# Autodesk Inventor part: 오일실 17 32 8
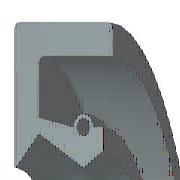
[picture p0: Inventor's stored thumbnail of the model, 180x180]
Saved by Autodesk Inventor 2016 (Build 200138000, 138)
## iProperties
IsCustomPart: 1
Created: 2012-02
Part Number: 오일실 17 32 8
Material: 고무
Description: 오일-실
Document SubType Name: Modeling
Standard: KS B 2804
Designer: mduedu
Standards Organization: KS
Language: ko-KR
Size Designation: D - 17 32 8
Categories: <MemberInstance><Categories><Category DisplayName="샤프트 부품" InternalName="7f7aeb1f-a693-4053-b835-cee3144e0d98" Mnemonic="SHFT"><Category DisplayName="실링" Intern
Density: 0.93 g/cm^3
Appearance: 고무 - 검은색 - 버전 1.1
Author: mduedu
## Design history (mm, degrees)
revolve "본체" stored, may be unused: angle "d17" = 90 deg
revolve "스프링1" stored, may be unused: angle "d18" = 90 deg
body "Solid1"
sketch "스케치1"
  geometry: L1 (0, 16)-(8, 16); L2 (8, 14.25)-(1.75, 14.25); L3 (1.75, 10.25)-(4.9, 8.5); L4 (4.9, 8.5)-(0, 8.5); L5 (0, 0)-(9.586, 0) reference; L6 (4.9, 8.5)-(6.3, 9.375); L7 (0, 18)-(0, -3) reference; L8 (-1.941, 0)-(11.507, 0) reference; L9 (4.2, 10.6)-(1.75, 11.21); L10 (1.75, 11.21)-(1.75, 14.25); L11 (0, 16)-(0, 8.588); L12 (4.9, 8.5)-(0, 8.5); L13 (1.75, 10.25)-(0.152, 8.528); L14 (8, 16)-(8, 14.25); L15 (5.6, 10.6)-(6.3, 10.6); L16 (6.3, 10.6)-(6.3, 9.375); C1 r 0.455 at (4.9, 10.6); A1 r 0.7 centre (4.9, 10.6) between (5.6, 10.6) and (4.2, 10.6); A2 r 0.088 centre (0.088, 8.588) between (0, 8.588) and (0.152, 8.528); 1 further point
  constraints: 28 end point, 5 horizontal alignment, 5 point on line, 4 point on circle, 4 vertical alignment, 3 centre point, 3 tangent, 2 collinear, 2 horizontal, 2 perpendicular, 1 coincident, 1 parallel
  dimensions: "d0" = 32 diameter of L1 L5 (= SD2); "d1" = 1.75 distance of L1.end L2.start (= SD); "d2" = 0.91 diameter of C1 (= SPDI); "d3" = 1.4 diameter of A1 (= SPDA); "d4" = 17 diameter of L3.end L5 (= NND); "d5" = 20.5 diameter of L3.start L5 (= TKDM); "d7" = 22.42 diameter of L9.end L5 (= TKDM + 0.24 x SWDT); "d8" = 1.75 distance between parallel lines of L11 L10 (= SD); "d9" = 4.9 distance from line of L11 C1.centre (= SPDST); "d10" = 21.2 diameter of C1.centre L5 (= HLDM); "d11" = 0.0875 radius of A2 (= 0.25 x LAB); "d12" = 6.3 distance between parallel lines of L11 L16 (= SDI); "d13" = 18.75 diameter of L6.end L5 (= ABDM); "d14" = 8 distance from line of L11 L1.end (= SWDT)
fillet "모깎기1" dims "d6" = 0.3 (= RR)
other parameters: "SD2" = 32 [user parameter; used in 1 equation term], "SWDT" = 8 [user parameter; used in 2 equation terms], "RR" = 0.3 [user parameter; used in 1 equation term], "SD" = 1.75 [user parameter; used in 2 equation terms], "NND" = 17 [user parameter; used in 1 equation term], "SPDA" = 1.4 [user parameter; used in 1 equation term], "SPDI" = 0.91 [user parameter; used in 1 equation term], "TKDM" = 20.5 [user parameter; used in 2 equation terms], "HLDM" = 21.2 [user parameter; used in 1 equation term], "ABDM" = 18.75 [user parameter; used in 1 equation term], "SDI" = 6.3 [user parameter; used in 1 equation term], "SPDST" = 4.9 [user parameter; used in 1 equation term], "LAB" = 0.35 [user parameter; used in 1 equation term], "d15" = 0, "d16" = 0, "d19" = 0
